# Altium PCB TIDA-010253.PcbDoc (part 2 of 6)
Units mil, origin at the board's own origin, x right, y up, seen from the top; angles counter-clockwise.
Board outline 5525 x 6695 mil, 4 copper layers (Top Layer, Signal Layer 1, Signal Layer 2, Bottom Layer), stack 61.2 mil thick; 522 components, 391 nets, 1722 pads, 1048 vias.
Unrouted connection lines stored in the file: 22.
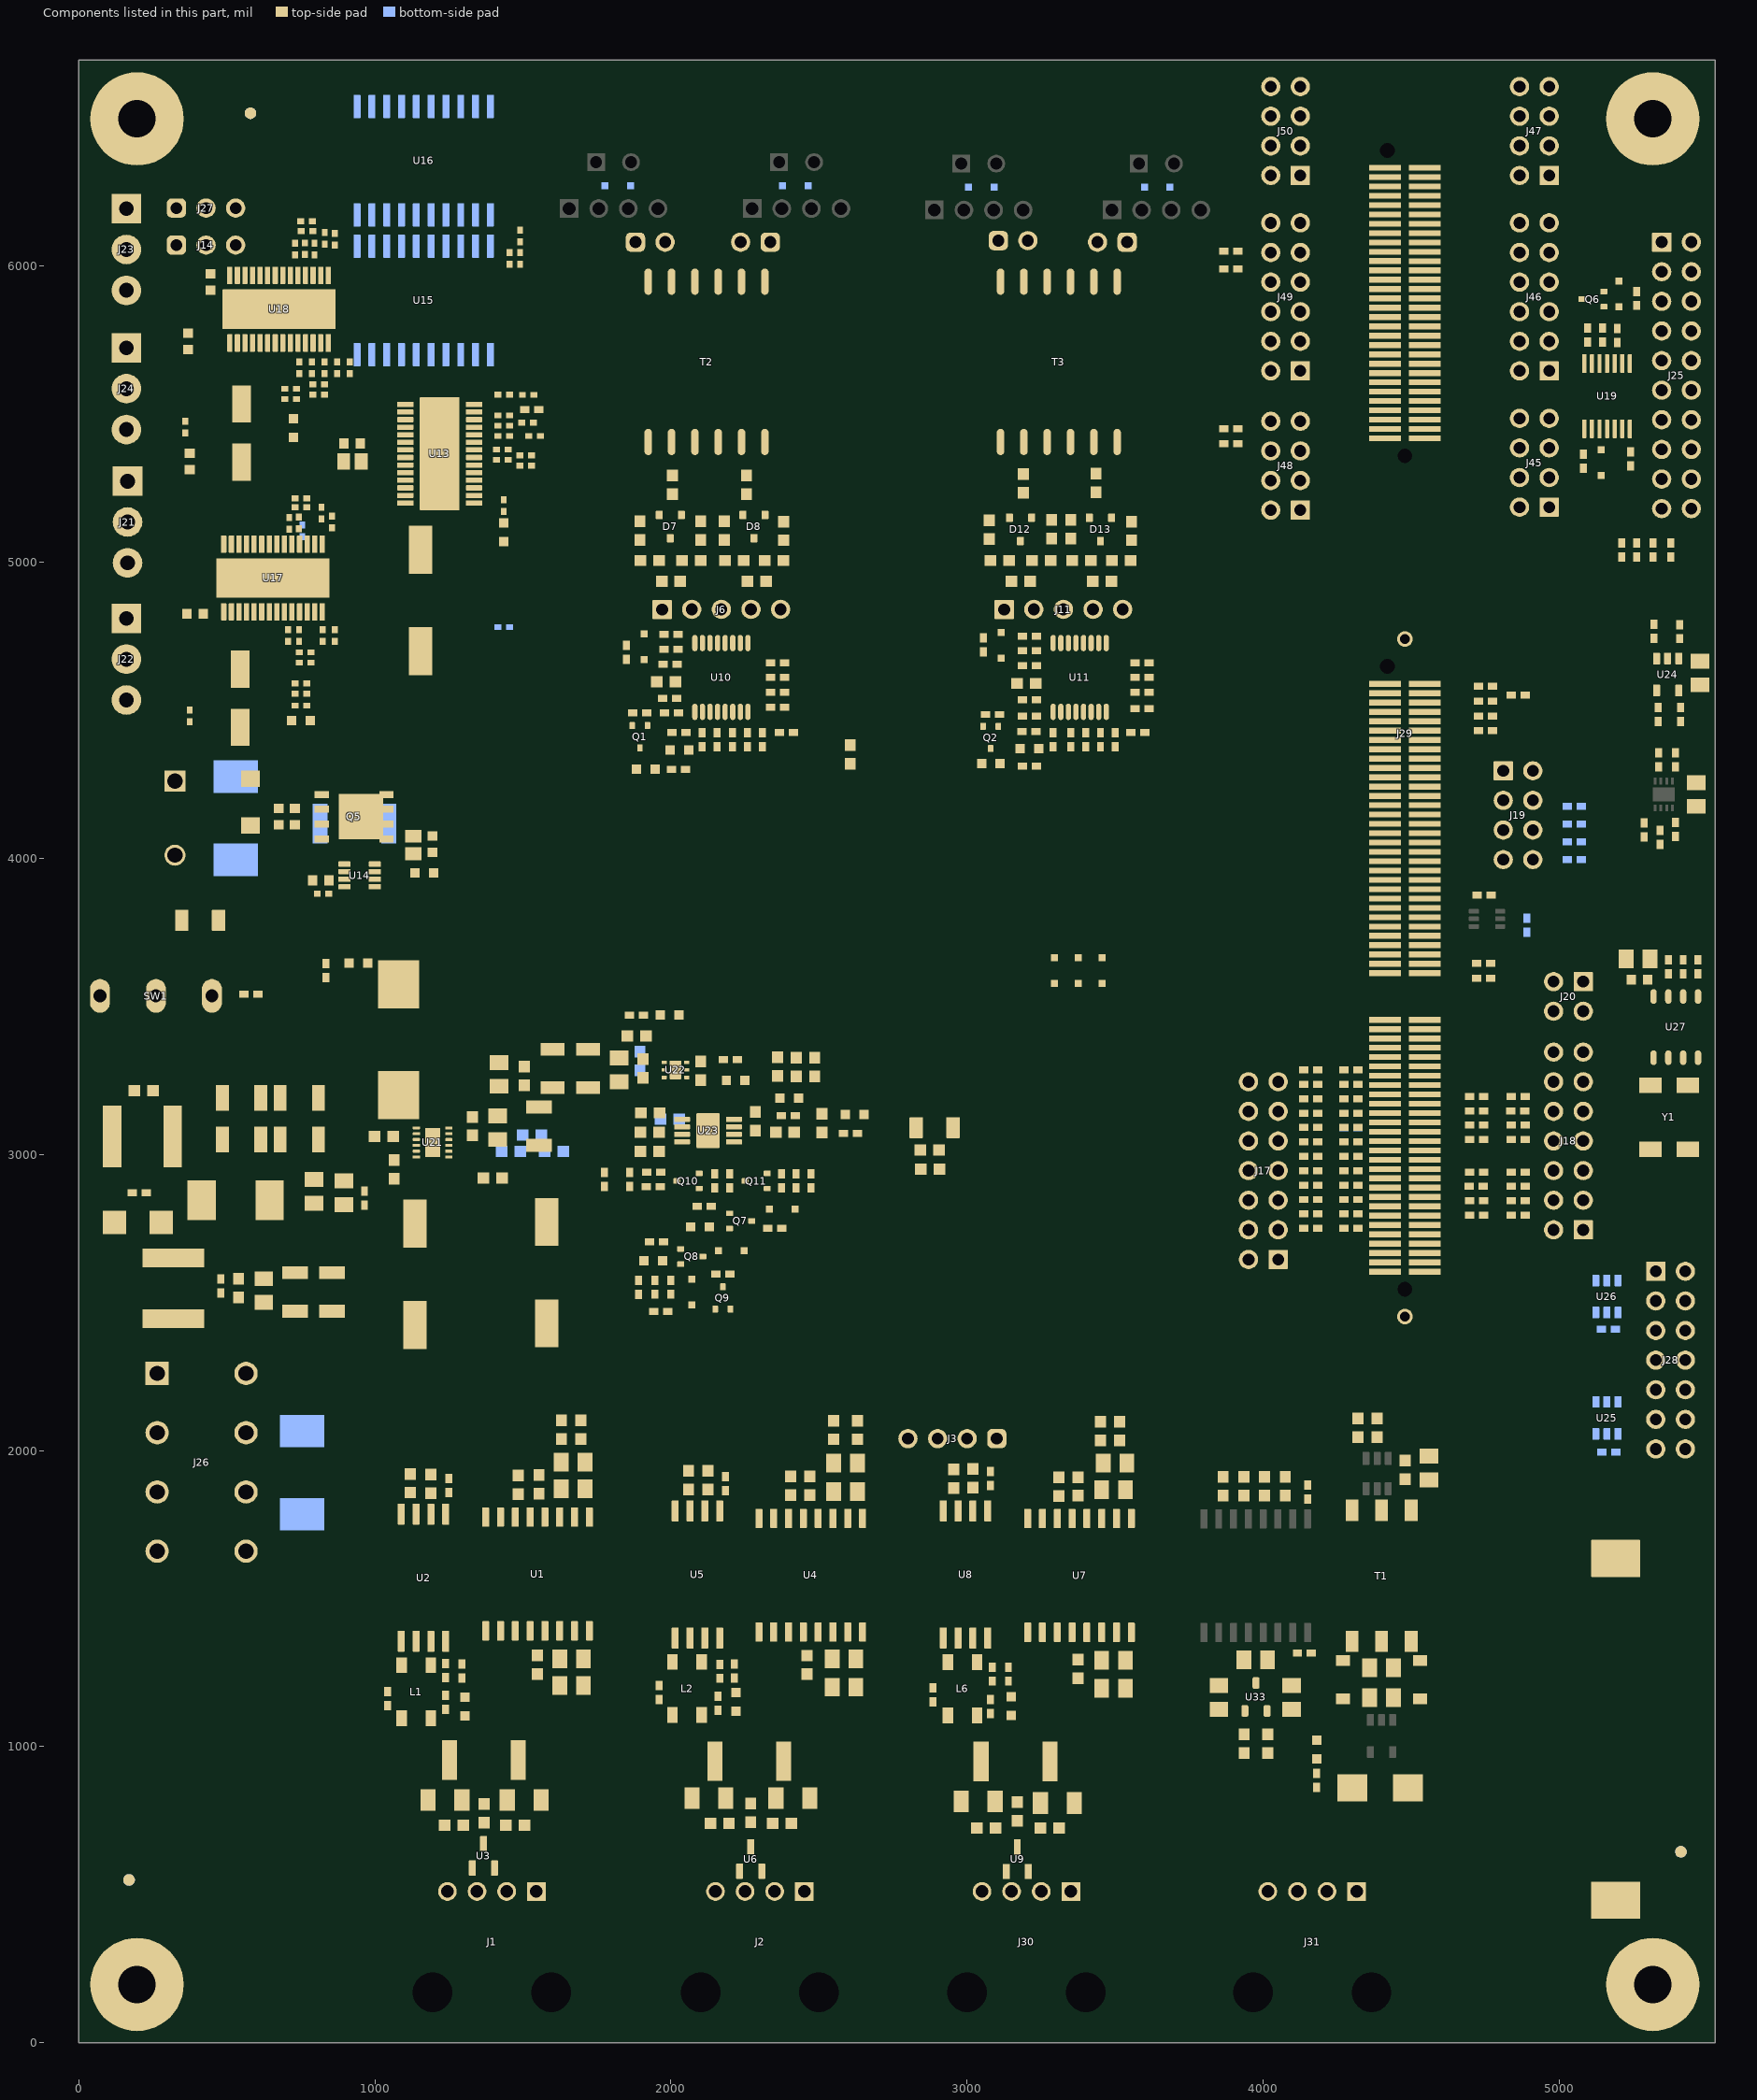
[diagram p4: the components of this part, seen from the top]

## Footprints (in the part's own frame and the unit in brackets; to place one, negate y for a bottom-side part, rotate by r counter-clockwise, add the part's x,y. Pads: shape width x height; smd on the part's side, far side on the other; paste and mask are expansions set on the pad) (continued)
FP-BU2032SM-G_SMT2-MFG [mm]
  rrect3% 3.2x4.2 smd paste+0 mask+0: 1(14.65,0) 2(-14.65,0)
  silkscreen extent -15.8,-8.25 14.55,8.25, body extent -15.8,-8 15.8,8, height 5.7
FP-DW0020A-MFG [mm]
  rrect17% 2x0.6 smd paste+0 mask+0: 1(-4.65,5.715) 2(-4.65,4.445) 3(-4.65,3.175) 4(-4.65,1.905) 5(-4.65,0.635) 6(-4.65,-0.635) 7(-4.65,-1.905) 8(-4.65,-3.175) 9(-4.65,-4.445) 10(-4.65,-5.715) 11(4.65,-5.715) 12(4.65,-4.445) 13(4.65,-3.175) 14(4.65,-1.905) 15(4.65,-0.635) 16(4.65,0.635) 17(4.65,1.905) 18(4.65,3.175) 19(4.65,4.445) 20(4.65,5.715)
  silkscreen extent -6.35,-6.5 3.27,6.5, body extent -5.16,-6.4 5.17,6.4, height 2.65
FP-GRM32ER71A476ME15L_1210-MFG [mm]
  rrect9% 1.1x2.05 smd paste+0 mask+0: 1(-1.65,0) 2(1.65,0)
  silkscreen extent -0.72,-1.35 0.72,1.35, body extent -2.3,-1.45 2.3,1.45, height 0.25
FP-PESD5V0L2BT,215_SOT23-3-MFG [mm]
  rrect17% 0.7x0.6 smd paste-1000 mask+0: 1(-1,0.95) 2(-1,-0.95) 3(1,0)
  body extent -1.5,-1.65 1.5,1.65, height 0.25
HEADER_HSEC8_180_DV [mm]
  rect 0.5x2.724 smd mask+0.076: 1(0,0) 2(0,3.4) 3(0.8,0) 4(0.8,3.4) 5(1.6,0) 6(1.6,3.4) 7(2.4,0) 8(2.4,3.4) 9(3.2,0) 10(3.2,3.4) 11(4,0) 12(4,3.4) 13(4.8,0) 14(4.8,3.4) 15(5.6,0) 16(5.6,3.4) 17(6.4,0) 18(6.4,3.4) 19(7.2,0) 20(7.2,3.4) 21(8,0) 22(8,3.4) 23(8.8,0) 24(8.8,3.4) 25(9.6,0) 26(9.6,3.4) 27(10.4,0) 28(10.4,3.4) 29(11.2,0) 30(11.2,3.4) 31(12,0) 32(12,3.4) 33(12.8,0) 34(12.8,3.4) 35(13.6,0) 36(13.6,3.4) 37(14.4,0) 38(14.4,3.4) 39(15.2,0) 40(15.2,3.4) 41(16,0) 42(16,3.4) 43(16.8,0) 44(16.8,3.4) 45(17.6,0) 46(17.6,3.4) 47(18.4,0) 48(18.4,3.4) 49(19.2,0) 50(19.2,3.4) 51(20,0) 52(20,3.4) 53(20.8,0) 54(20.8,3.4) 55(21.6,0) 56(21.6,3.4) 57(25.6,0) 58(25.6,3.4) 59(26.4,0) 60(26.4,3.4) 61(27.2,0) 62(27.2,3.4) 63(28,0) 64(28,3.4) 65(28.8,0) 66(28.8,3.4) 67(29.6,0) 68(29.6,3.4) 69(30.4,0) 70(30.4,3.4) 71(31.2,0) 72(31.2,3.4) 73(32,0) 74(32,3.4) 75(32.8,0) 76(32.8,3.4) 77(33.6,0) 78(33.6,3.4) 79(34.4,0) 80(34.4,3.4) 81(35.2,0) 82(35.2,3.4) 83(36,0) 84(36,3.4) 85(36.8,0) 86(36.8,3.4) 87(37.6,0) 88(37.6,3.4) 89(38.4,0) 90(38.4,3.4) 91(39.2,0) 92(39.2,3.4) 93(40,0) 94(40,3.4) 95(40.8,0) 96(40.8,3.4) 97(41.6,0) 98(41.6,3.4) 99(42.4,0) 100(42.4,3.4) 101(43.2,0) 102(43.2,3.4) 103(44,0) 104(44,3.4) 105(44.8,0) 106(44.8,3.4) 107(45.6,0) 108(45.6,3.4) 109(46.4,0) 110(46.4,3.4) 111(47.2,0) 112(47.2,3.4) 113(48,0) 114(48,3.4) 115(48.8,0) 116(48.8,3.4) 117(49.6,0) 118(49.6,3.4) 119(50.4,0) 120(50.4,3.4) 121(71.468,0) 122(71.468,3.4) 123(72.268,0) 124(72.268,3.4) 125(73.068,0) 126(73.068,3.4) 127(73.868,0) 128(73.868,3.4) 129(74.668,0) 130(74.668,3.4) 131(75.468,0) 132(75.468,3.4) 133(76.268,0) 134(76.268,3.4) 135(77.068,0) 136(77.068,3.4) 137(77.868,0) 138(77.868,3.4) 139(78.668,0) 140(78.668,3.4) 141(79.468,0) 142(79.468,3.4) 143(80.268,0) 144(80.268,3.4) 145(81.068,0) 146(81.068,3.4) 147(81.868,0) 148(81.868,3.4) 149(82.668,0) 150(82.668,3.4) 151(83.468,0) 152(83.468,3.4) 153(84.268,0) 154(84.268,3.4) 155(85.068,0) 156(85.068,3.4) 157(85.868,0) 158(85.868,3.4) 159(86.668,0) 160(86.668,3.4) 161(87.468,0) 162(87.468,3.4) 163(88.268,0) 164(88.268,3.4) 165(89.068,0) 166(89.068,3.4) 167(89.868,0) 168(89.868,3.4) 169(90.668,0) 170(90.668,3.4) 171(91.468,0) 172(91.468,3.4) 173(92.268,0) 174(92.268,3.4) 175(93.068,0) 176(93.068,3.4) 177(93.868,0) 178(93.868,3.4) 179(94.668,0) 180(94.668,3.4)
  round 0.025 hole 1.27 unplated mask+0.876: 181(-1.5,1.7) 182(51.9,3.2) 183(69.968,1.7) 184(96.168,3.2)
  round 1.348 hole 0.84: 185(-3.85,1.7) 186(54.25,1.7)
  silkscreen extent -8.76,-2.18 97.75,5.58
HMU2129NL [mm] "SOP, 12-Leads, Body 14.65x11.50mm, Pitch 2.00mm, IPC Low Density"
  oval 2.25x0.65 smd: 1(-6.875,5) 2(-6.875,3) 3(-6.875,1) 4(-6.875,-1) 5(-6.875,-3) 6(-6.875,-5) 7(6.875,-5) 8(6.875,-3) 9(6.875,-1) 10(6.875,1) 11(6.875,3) 12(6.875,5)
  silkscreen extent -7,-7.35 5.35,7.35
IEC_HighVoltage_Small [mil]
  silkscreen extent -107,-88 107,97
IHLP-2525CZ-5A [mil] "Vishay Dale recommended land pattern"
  rect 95x135 smd: 1(-114.96,0) 2(114.96,0)
  silkscreen extent -145,-136 145,136, body extent -143,-134 143,134, height 118
KF142R-5.08-4p [mm]
  round 2 hole 1.3: 1(0,7.62) 2(5.08,7.62) 2(5.08,0) 3(10.16,7.62) 3(10.16,0) 4(15.24,0) 4(15.24,7.62)
  rect 2x2 hole 1.3: 1(0,0)
  silkscreen extent -1.9,-4.2 22.04,9.45, body extent -0.76,-4.2 22.1,9.4, height 12.7
Label_650x200 [mil] "Thermal Transfer Label"
  round 1 on Mech13: 0(0,0)
  silkscreen extent -325,-100 325,100, body extent -325,-100 325,100, height 1
Molex_70551-0038 [mm] "Header(shrouded), 2.54mm, 4x1, R/A, TH"
  rect 1.6x1.6 hole 1.09: 1(0,3.81)
  round 1.6 hole 1.09: 2(0,1.27) 3(0,-1.27) 4(0,-3.81)
  round 0 hole 3.4 unplated paste+0 mask+0: MH1(8.64,-5.08) MH2(8.64,5.08)
  silkscreen extent 1.45,-6.98 12.88,7.32, body extent -0.71,-6.98 12.88,6.98, height 6.6
"NY PMS 440 0025 PH" [mm] "4-40 nylon screw and mounting hole"
  round 8 hole 3.2: 1(0,0)
  body extent -3.3,-3.3 3.3,3.3, height 2.69
Pb-Free_Overlay_Small [mil]
  silkscreen extent -46,-46 46,46
Phoenix_1714955 [mm] "Terminal Block, 2x1, 6.35mm, TH"
  rect 1.8x1.8 hole 1.3: 1(-3.175,0)
  round 1.8 hole 1.3: 2(3.175,0)
  silkscreen extent -6.7,-7.9 6.35,4.6, body extent -6.92,-7.9 6.35,4.6, height 21.5
PowerPAK_SO-8 [mil] "Vishay PowerPAK SO-8, Body 5.3x6.0mm (max), Pitch 1.27mm, IPC Medium Density"
  rect 50x24 smd mask+2.99: 1(-109.5,75) 2(-109.5,25) 3(-109.5,-25) 4(-109.5,-75)
  rect 48x24 smd mask+2.99: 5(109.5,-75) 8(109.5,75)
  rect 48x24 smd paste-12 mask+2.99: 6(109.5,-25) 7(109.5,25)
  rect 150x154 smd paste-75 mask+2.99: 9(22.5,0)
  silkscreen extent -130,-104 59,104, body extent -121,-102 121,101, height 43
PW0014A-MFG [mm]
  rrect29% 1.6x0.35 smd paste-1000 mask+0: 1(-2.8,1.95) 2(-2.8,1.3) 3(-2.8,0.65) 4(-2.8,0) 5(-2.8,-0.65) 6(-2.8,-1.3) 7(-2.8,-1.95) 8(2.8,-1.95) 9(2.8,-1.3) 10(2.8,-0.65) 11(2.8,0) 12(2.8,0.65) 13(2.8,1.3) 14(2.8,1.95)
  silkscreen extent -4.32,-2.55 2.25,2.55, body extent -3.7,-2.8 3.7,2.8, height 0.25
PW0016A_N [mm] "TSOP, 16-Leads, Body 5x4.4mm, Pitch 0.65mm, IPC Medium Density"
  oval 1.4x0.45 smd: 1(-2.95,2.275) 2(-2.95,1.625) 3(-2.95,0.975) 4(-2.95,0.325) 5(-2.95,-0.325) 6(-2.95,-0.975) 7(-2.95,-1.625) 8(-2.95,-2.275) 9(2.95,-2.275) 10(2.95,-1.625) 11(2.95,-0.975) 12(2.95,-0.325) 13(2.95,0.325) 14(2.95,0.975) 15(2.95,1.625) 16(2.95,2.275)
  silkscreen extent -3.5,-2.55 1.85,2.75, body extent -3.21,-2.5 3.21,2.5, height 1
PWP0028C_N [mm] "TSOP, 28-Leads, Body 9.7x4.4mm, Pitch 0.65mm, Exposed Pad, IPC Medium Density"
  rrect22% 1.4x0.45 smd: 1(-2.95,4.225) 2(-2.95,3.575) 3(-2.95,2.925) 4(-2.95,2.275) 5(-2.95,1.625) 6(-2.95,0.975) 7(-2.95,0.325) 8(-2.95,-0.325) 9(-2.95,-0.975) 10(-2.95,-1.625) 11(-2.95,-2.275) 12(-2.95,-2.925) 13(-2.95,-3.575) 14(-2.95,-4.225) 15(2.95,-4.225) 16(2.95,-3.575) 17(2.95,-2.925) 18(2.95,-2.275) 19(2.95,-1.625) 20(2.95,-0.975) 21(2.95,-0.325) 22(2.95,0.325) 23(2.95,0.975) 24(2.95,1.625) 25(2.95,2.275) 26(2.95,2.925) 27(2.95,3.575) 28(2.95,4.225)
  rrect3% 3.4x9.7 smd paste-1.7 mask-1.7: 29(0,0)
  rrect3% 3.1x5.18 on Top Solder: 29(0,0)
  rrect3% 3.1x5.18 on Top Paste: 29(0,0)
  silkscreen extent -3.5,-4.9 2,4.9, body extent -3.2,-4.85 3.2,4.85, height 1.13
PWP0028R-MFG [mm]
  rrect22% 1.5x0.45 smd paste+0 mask+0: 1(-2.9,4.225) 2(-2.9,3.575) 3(-2.9,2.925) 4(-2.9,2.275) 5(-2.9,1.625) 6(-2.9,0.975) 7(-2.9,0.325) 8(-2.9,-0.325) 9(-2.9,-0.975) 10(-2.9,-1.625) 11(-2.9,-2.275) 12(-2.9,-2.925) 13(-2.9,-3.575) 14(-2.9,-4.225) 15(2.9,-4.225) 16(2.9,-3.575) 17(2.9,-2.925) 18(2.9,-2.275) 19(2.9,-1.625) 20(2.9,-0.975) 21(2.9,-0.325) 22(2.9,0.325) 23(2.9,0.975) 24(2.9,1.625) 25(2.9,2.275) 26(2.9,2.925) 27(2.9,3.575) 28(2.9,4.225)
  rrect3% 3.4x9.7 smd paste-1000 mask-1000: 29(0,0)
  silkscreen extent -4.37,-4.9 2.25,4.9, body extent -3.75,-5.15 3.75,5.15, height 0.25
SM_RADIAL_D [mm] "6.3 x 5.8mm:  Panasonic D"
  rect 3.2x1.6 smd: 1(-2.5,0) 2(2.5,0)
  silkscreen extent -3.4,-3.4 3.4,3.4, body extent -3.4,-3.4 3.4,3.4, height 6.1
SM_RADIAL_G [mm] "10 x 10.2mm:  Panasonic G"
  rect 4.1x2 smd: 1(-4.35,0) 2(4.35,0)
  silkscreen extent -5.35,-5.35 5.35,5.35, body extent -5.25,-5.25 5.25,5.25, height 10.5
SMA [mm] "Molded Diode, 2-Leads, Body 4.3x2.6mm, IPC Medium Density, based on OnSemi component dimensions and land pattern"
  rect 2x2 smd: 1(-2,0) 2(2,0)
  silkscreen extent -3.66,-1.57 2.79,1.57, body extent -2.6,-1.3 2.6,1.3, height 2.42
SMA_Bi [mm] "SMD, 2-Leads, Body 4.275x2.575mm"
  rect 1.4x1.64 smd: 1(-2.015,0) 2(2.015,0)
  silkscreen extent -2.3,-1.45 2.3,1.45, body extent -2.52,-1.45 2.52,1.45, height 2.65
SMC_Bi [mil] "SMC, no polarity mark"
  rect 110x150 smd: 1(-140.49,0) 2(140.49,0)
  body extent -156,-116 156,116, height 92
SOD-123 [mm] "On Semi recommended land pattern"
  rect 0.915x1.22 smd: 1(-1.637,0) 2(1.637,0)
  silkscreen extent -2.74,-1.17 2.03,1.17, body extent -1.93,-0.9 1.93,0.9, height 1.35
SOD-323 [mm] "NXP recommended land pattern"
  rect 0.6x0.6 smd paste-0.05: 1(-1.1,0) 2(1.1,0)
  silkscreen extent -2.06,-0.86 1.53,0.86, body extent -1.3,-0.67 1.3,0.68, height 1.1
SOD-323-Bi [mm] "SOD323, 2-Leads, Body 1.9x1.45mm, No Polarity Mark"
  rect 0.6x0.6 smd paste-0.05: 1(-1.1,0) 2(1.1,0)
  silkscreen extent -1.53,-0.77 1.53,0.77, body extent -1.27,-0.65 1.27,0.65, height 1.02
SOT-23 [mm] "SOT23, 3-Leads, Body 2.9x1.3mm, Pitch 0.95mm, Lead Span 2.5mm, IPC Medium Density"
  rrect50% 1x0.6 smd: 1(-1.2,0.95) 2(-1.2,-0.95) 3(1.2,0)
  silkscreen extent -1.62,-1.5 0.7,1.5, body extent -1.16,-1.45 1.21,1.45, height 1
SOT-323 [mm] "Diodes Inc recommended land pattern.  2016-02-24"
  rrect21% 0.6x0.47 smd: 1(-0.95,0.65) 2(-0.95,-0.65) 3(0.95,0)
  silkscreen extent -1.14,-1.22 0.77,1.22, body extent -1.13,-1.13 1.12,1.12, height 1.13
SS12D10 [mm]
  oval 1.7x2.9 hole 1.1 slot 2.3 at 90 deg paste+0 mask+0.05: 1(-4.8,0) 2(0,0) 3(4.8,0)
  silkscreen extent -6.5,-3.5 6.5,3.5, body extent -6.5,-3.4 6.5,3.4, height 16.4
TERM_BLK_ED555-3DS [mm]
  rect 2.54x2.54 hole 1.27: 1(0,0)
  round 2.54 hole 1.27: 2(3.5,0) 3(7,0)
  silkscreen extent -2.36,-4.09 8.75,2.67, body extent -1.75,-3.83 8.75,2.67, height 8.2
TSW-102-07-G-D [mm] "Samtec 100mil, 2x2, 230 mil above insulator"
  rrect6% 1.65x1.65 hole 1.016: 1(-1.27,-1.27)
  round 1.65 hole 1.016: 2(-1.27,1.27) 3(1.27,-1.27) 4(1.27,1.27)
  silkscreen extent -3.57,-2.54 2.54,2.54, body extent -2.54,-2.54 2.54,2.54, height 8.38
TSW-102-07-G-S [mm] "Samtec 100mil, 1x2, 230 mil above insulator"
  rrect50% 1.65x1.65 hole 1.016: 1(-1.27,0)
  round 1.65 hole 1.016: 2(1.27,0)
  silkscreen extent -3.17,-1.27 2.54,1.27, body extent -2.54,-1.27 2.54,1.27, height 8.38
TSW-103-07-G-S [mm] "Samtec 100mil, 1x3, 230 mil above insulator"
  rrect50% 1.65x1.65 hole 1.016: 1(-2.54,0)
  round 1.65 hole 1.016: 2(0,0) 3(2.54,0)
  body extent -3.81,-1.27 3.81,1.27, height 8.38
TSW-104-07-G-D [mm] "Samtec 100mil, 2x4, 230 mil above insulator"
  rrect6% 1.65x1.65 hole 1.016: 1(-3.81,-1.27)
  round 1.65 hole 1.016: 2(-3.81,1.27) 3(-1.27,-1.27) 4(-1.27,1.27) 5(1.27,-1.27) 6(1.27,1.27) 7(3.81,-1.27) 8(3.81,1.27)
  silkscreen extent -6.1,-2.54 5.08,2.54, body extent -5.08,-2.54 5.08,2.54, height 8.38
TSW-104-07-G-S [mm] "Samtec 100mil, 1x4, 230 mil above insulator"
  rrect50% 1.65x1.65 hole 1.016: 1(-3.81,0)
  round 1.65 hole 1.016: 2(-1.27,0) 3(1.27,0) 4(3.81,0)
  body extent -5.08,-1.27 5.08,1.27, height 8.38
TSW-105-07-X-S [mm] "Samtec 100mil, 1x5, 230 mil above insulator"
  rrect6% 1.65x1.65 hole 1.016: 1(-5.08,-0.025)
  round 1.65 hole 1.016: 2(-2.54,0) 3(0,0) 4(2.54,0) 5(5.08,0)
  silkscreen extent -7.05,-1.25 6.37,1.25, body extent -6.35,-1.27 6.35,1.27, height 8.38
TSW-106-07-G-D [mm] "Samtec 100mil, 2x6, 230 mil above insulator"
  rrect6% 1.65x1.65 hole 1.016: 1(-6.35,-1.27)
  round 1.65 hole 1.016: 2(-6.35,1.27) 3(-3.81,-1.27) 4(-3.81,1.27) 5(-1.27,-1.27) 6(-1.27,1.27) 7(1.27,-1.27) 8(1.27,1.27) 9(3.81,-1.27) 10(3.81,1.27) 11(6.35,-1.27) 12(6.35,1.27)
  silkscreen extent -8.64,-2.54 7.62,2.54, body extent -7.62,-2.54 7.62,2.54, height 8.38
TSW-107-07-X-D [mm] "Samtec 100mil, 2x7, 230 mil above insulator"
  rrect6% 1.65x1.65 hole 1.016: 1(-7.62,-1.27)
  round 1.65 hole 1.016: 2(-7.62,1.27) 3(-5.08,-1.27) 4(-5.08,1.27) 5(-2.54,-1.27) 6(-2.54,1.27) 7(0,-1.27) 8(0,1.27) 9(2.54,-1.27) 10(2.54,1.27) 11(5.08,-1.27) 12(5.08,1.27) 13(7.62,-1.27) 14(7.62,1.27)
  silkscreen extent -9.91,-2.53 9.14,2.5, body extent -8.89,-2.54 8.89,2.54, height 8.38
TSW-110-07-G-D [mm] "Samtec 100mil, 2x10, 230 mil above insulator"
  rrect6% 1.65x1.65 hole 1.016: 1(-11.43,-1.27)
  round 1.65 hole 1.016: 2(-11.43,1.27) 3(-8.89,-1.27) 4(-8.89,1.27) 5(-6.35,-1.27) 6(-6.35,1.27) 7(-3.81,-1.27) 8(-3.81,1.27) 9(-1.27,-1.27) 10(-1.27,1.27) 11(1.27,-1.27) 12(1.27,1.27) 13(3.81,-1.27) 14(3.81,1.27) 15(6.35,-1.27) 16(6.35,1.27) 17(8.89,-1.27) 18(8.89,1.27) 19(11.43,-1.27) 20(11.43,1.27)
  silkscreen extent -13.72,-2.54 12.7,2.54, body extent -12.7,-2.54 12.7,2.54, height 8.38
WE-LHMI_1040 [mm] "Wurth"
  rect 4.1x3.5 smd: 1(-4.75,0) 2(4.75,0)
  silkscreen extent -5.5,-5.15 5.5,5.15, body extent -5.5,-5.15 5.5,5.15, height 4
WEEE_Minimum [mil] "WEEElie bin"
  silkscreen extent -95,-172 99,104
WL-SMCW_GREEN [mm] "WURTH"
  rect 0.8x0.8 smd: 1(-0.8,0) 2(0.8,0)
  silkscreen extent -1.9,-0.8 1.2,0.8, body extent -0.85,-0.45 0.85,0.45, height 0.8
WL-SMCW_RED [mm] "WURTH"
  rect 0.8x0.8 smd: 1(-0.8,0) 2(0.8,0)
  silkscreen extent -1.9,-0.8 1.2,0.8, body extent -0.85,-0.45 0.85,0.45, height 0.8
Wurth_750315371 [mm] "SMD, Body 12.6x8.3mm, Pitch 2.54mm"
  rect 1.83x1.09 smd: 1(-5.62,2.54) 2(-5.62,0) 3(-5.62,-2.54) 4(5.62,-2.54) 5(5.62,0) 6(5.62,2.54)
  silkscreen extent -6.3,-4.15 6.3,4.4, body extent -6.35,-4.2 6.35,4.2, height 4.11
XTAL_MC-306 [mm] "SEIKO-EPSON"
  rect 1.9x1.3 smd: 1(-1.6,2.75) 2(-1.6,-2.75) 3(1.6,-2.75) 4(1.6,2.75)
  silkscreen extent -1.6,-4 1.6,4, body extent -1.6,-4 1.6,4, height 2.55

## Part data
BT1: library part CMP-0032780-1, "Battery Holder Coin 20MM SMD", Digikey Part Number=BU2032SM-GCT-ND, Manufacturer=MPD, Operating Temperature Range="-40°C to +280°C"
C1 C2 C8 C9 C15 C16 C109 C110 C111 C112 C117 C118 C119 C120 C121 C122 C123 C124 C125 C128 C129 C131 C132 C133 C134 C138 C139 C144 C145 C146 C147: library part CMP-0006350-2, "CAP, CERM, 0.1 uF, 10 V, +/- 10%, X7R, AEC-Q200 Grade 1, 0402", Cap_Case=0402, Manufacturer=MuRata, Supplier Part Number 1=81-GCM155R71A104K5D, TempCo=X7R, Tolerance_%=10%, Value1=Unknown, Value2=10V, ValueDisplayed=0.1uF
C3 C4 C10 C11 C17 C18 C140 C141: library part CMP-0007995-2, "CAP, CERM, 10 uF, 16 V, +/- 10%, X7R, 0805", Cap_Case=0805, Manufacturer="Samsung Electro-Mechanics", TempCo=X7R, Tolerance_%=10%, Value1=Unknown, Value2=16V, ValueDisplayed=10uF
C5 C7 C12 C14 C135 C137: library part CMP-0007280-4, "CAP, CERM, 68 pF, 100 V, +/- 5%, C0G/NP0, 0603", Cap_Case=0603, Manufacturer=MuRata, Supplier Part Number 1=490-1347-1-ND, TempCo=C0G/NP0, Tolerance_%=5%, Value1=Unknown, Value2=100V, ValueDisplayed=68pF
C6 C13 C136: library part CMP-0007456-1, "CAP, CERM, 4700 pF, 50 V, +/- 10%, X7R, 0603", Cap_Case=0603, Manufacturer=MuRata, Supplier Part Number 1=490-1506-1-ND, TempCo=X7R, Tolerance_%=10%, Value1=Unknown, Value2=50V, ValueDisplayed=4700pF
C19 C25 C30 C36 C75 C101 C105 C106: library part CMP-0006356-2, "CAP, CERM, 0.1 uF, 50 V, +/- 10%, X7R, AEC-Q200 Grade 1, 0402", Cap_Case=0402, Manufacturer=MuRata, Supplier Part Number 1=490-10672-1-ND, TempCo=X7R, Tolerance_%=10%, Value1=Unknown, Value2=50V, ValueDisplayed=0.1uF
C20 C24 C26 C28 C31 C35 C37 C39: library part CMP-0860329-1, "CAP, CERM, 220 pF, 50 V,+/- 5%, X7R, 0603", Cap_Case=0603, Manufacturer="Samsung Electro-Mechanics", TempCo=X7R, Tolerance_%=5%, Value2=50V, ValueDisplayed=220pF
C21 C27 C32 C38: library part CMP-0750041-1, "CAP, CERM, 100 pF, 50 V,+/- 5%, C0G/NP0, AEC-Q200 Grade 1, 0603", Cap_Case=0603, Manufacturer=MuRata, TempCo=C0G/NP0, Tolerance_%=5%, Value2=50V, ValueDisplayed=100pF
C22 C23 C33 C34: library part CMP-0078265-1, "CAP, CERM, 0.22 µF, 16 V,+/- 10%, X7R, AEC-Q200 Grade 1, 0402", Cap_Case=0402, Manufacturer=MuRata, Supplier Part Number 1=490-10671-1-ND, TempCo=X7R, Tolerance_%=10%, Value2=16V, ValueDisplayed=0.22µF
C29 C40: library part CMP-0006324-2, "CAP, CERM, 0.01 uF, 50 V, +/- 10%, X7R, AEC-Q200 Grade 1, 0402", Cap_Case=0402, Manufacturer=TDK, Supplier Part Number 1=445-6893-1-ND, TempCo=X7R, Tolerance_%=10%, Value1="0.333065 ohm", Value2=50V, ValueDisplayed=0.01uF
C47 C51: library part CMP-0006837-4, "CAP, CERM, 0.1 uF, 50 V, +/- 10%, X7R, 0603", Cap_Case=0603, Manufacturer="Wurth Elektronik", TempCo=X7R, Tolerance_%=10%, Value1=Unknown, Value2=50V, ValueDisplayed=0.1uF
C48 C53: library part CMP-0007857-1, "CAP, CERM, 2.2 uF, 50 V, +/- 10%, X6S, 0805", Cap_Case=0805, Manufacturer=TDK, Supplier Part Number 1=445-7597-1-ND, TempCo=X6S, Tolerance_%=10%, Value1="0.00366 ohm", Value2=50V, ValueDisplayed=2.2uF
C49: library part CMP-0006783-4, "CAP, CERM, 33 pF, 50 V, +/- 5%, C0G/NP0, 0603", Cap_Case=0603, Manufacturer=AVX, Supplier Part Number 1=478-1169-1-ND, TempCo=C0G/NP0, Tolerance_%=5%, Value1="0.209 ohm", Value2=50V, ValueDisplayed=33pF
C50: library part CMP-0006840-4, "CAP, CERM, 100 pF, 50 V, +/- 5%, C0G/NP0, 0603", Cap_Case=0603, Manufacturer=Kemet, Supplier Part Number 1=1414602, TempCo=C0G/NP0, Tolerance_%=5%, Value1=Unknown, Value2=50V, ValueDisplayed=100pF
C52 C108: library part CMP-0082523-1, "CAP, CERM, 1 µF, 25 V,+/- 10%, X7R, AEC-Q200 Grade 1, 0603", Cap_Case=0603, Manufacturer=TDK, Supplier Part Number 1=445-9819-1-ND, TempCo=X7R, Tolerance_%=10%, Value2=25V, ValueDisplayed=1µF
C54: library part CMP-0022330-4, "RES, 31.6 k, 1%, 0.1 W, AEC-Q200 Grade 0, 0603", Manufacturer=Vishay-Dale, Power_W=100mW, Supplier Part Number 1=541-31.6KHCT-ND, TempCo="100 ppm/C", Tolerance_%=1%, Value2=0.1W, Value_Code=31k6, ValueDisplayed=31.6k
C59: library part CMP-0011178-2, "CAP, AL, 150 uF, 50 V, +/- 20%, 0.18 ohm, AEC-Q200 Grade 2, SMD", Cap_Case=G, Manufacturer=Panasonic, Supplier Part Number 1=PCE3810CT-ND, Tolerance_%=20%, Value1="0.18 ohm", Value2=50V, ValueDisplayed=150uF
C60 C61: library part CMP-0011175-2, "CAP, AL, 10 uF, 50 V, +/- 20%, 0.88 ohm, AEC-Q200 Grade 2, SMD", Cap_Case=D, Manufacturer=Panasonic, Supplier Part Number 1=PCE3807CT-ND, Tolerance_%=20%, Value1="0.88 ohm", Value2=50V, ValueDisplayed=10uF
C62 C63 C64 C65: library part CMP-0064946-2, "CAP, CERM, 0.1 uF, 50 V,+/- 10%, X7R, 0402", Cap_Case=0402, Manufacturer=TDK, Supplier Part Number 1=445-173610-1-ND, TempCo=X7R, Tolerance_%=10%, Value1=Unknown, Value2=50V, ValueDisplayed=0.1uF
C66 C67 C68 C69 C70: library part CMP-0006691-2, "CAP, CERM, 470 pF, 50 V, +/- 10%, X7R, 0402", Cap_Case=0402, Manufacturer=MuRata, Supplier Part Number 1=490-1300-1-ND, TempCo=X7R, Tolerance_%=10%, Value1=Unknown, Value2=50V, ValueDisplayed=470pF
C71 C72 C73 C74: library part CMP-0006844-4, "CAP, CERM, 1000 pF, 50 V, +/- 5%, X7R, AEC-Q200 Grade 1, 0603", Cap_Case=0603, Manufacturer=Kemet, Supplier Part Number 1=399-12989-1-ND, TempCo=X7R, Tolerance_%=5%, Value1=Unknown, Value2=50V, ValueDisplayed=1000pF
C76 C77: library part CMP-0010742-1, "CAP, AL, 220 uF, 35 V, +/- 20%, 0.15 ohm, AEC-Q200 Grade 1, SMD", Cap_Case=10x10.2mm, Manufacturer=Panasonic, Supplier Part Number 1=PCE4935CT-ND, Tolerance_%=20%, Value1="0.15 ohm", Value2=35V, ValueDisplayed=220uF
C78: library part CMP-0007088-4, "CAP, CERM, 4700 pF, 100 V, +/- 10%, X7R, AEC-Q200 Grade 1, 0603", Cap_Case=0603, Manufacturer=TDK, Supplier Part Number 1=445-5810-1-ND, TempCo=X7R, Tolerance_%=10%, Value1="0.469862 ohm", Value2=100V, ValueDisplayed=4700pF
C79 C81: library part CMP-0009420-2, "CAP, CERM, 15 uF, 100 V, +/- 20%, X7S, AEC-Q200 Grade 1, 2220", Cap_Case=2220_280, Manufacturer=TDK, Supplier Part Number 1=445-7948-1-ND, TempCo=X7S, Tolerance_%=20%, Value1="0.002642 ohm", Value2=100V, ValueDisplayed=15uF
C80: library part CMP-0006412-2, "CAP, CERM, 1000 pF, 50 V, +/- 5%, C0G/NP0, 0402", Cap_Case=0402, Manufacturer=MuRata, Supplier Part Number 1=490-3244-1-ND, TempCo=C0G/NP0, Tolerance_%=5%, Value1=Unknown, Value2=50V, ValueDisplayed=1000pF
C82 C83 C87 C88 C89 C90: library part CMP-0009164-2, "CAP, CERM, 10 uF, 50 V, +/- 10%, X7S, AEC-Q200 Grade 1, 1210", Cap_Case=1210_280, Manufacturer=TDK, Supplier Part Number 1=445-7004-1-ND, TempCo=X7S, Tolerance_%=10%, Value1="0.002827 ohm", Value2=50V, ValueDisplayed=10uF
C84 C91 C92: library part CMP-0007977-2, "CAP, CERM, 2.2 uF, 50 V, +/- 10%, X7R, AEC-Q200 Grade 1, 0805", Cap_Case=0805, Manufacturer=TDK, Supplier Part Number 1=445-174216-1-ND, TempCo=X7R, Tolerance_%=10%, Value1="0.003288 ohm", Value2=50V, ValueDisplayed=2.2uF
C85: library part CMP-0084240-1, "CAP, CERM, 0.1 µF, 50 V,+/- 20%, X8R, AEC-Q200 Grade 0, 0603", Cap_Case=0603, Manufacturer=TDK, TempCo=X8R, Tolerance_%=20%, Value2=50V, ValueDisplayed=0.1µF
C86 C93: library part CMP-0006309-2, "CAP, CERM, 1000 pF, 50 V, +/- 5%, C0G/NP0, AEC-Q200 Grade 1, 0402", Cap_Case=0402, Manufacturer=TDK, Supplier Part Number 1=445-6885-1-ND, TempCo=C0G/NP0, Tolerance_%=5%, Value1=Unknown, Value2=50V, ValueDisplayed=1000pF
C96: library part CMP-0009162-2, "CAP, CERM, 4.7 uF, 50 V, +/- 10%, X7R, AEC-Q200 Grade 1, 1210", Cap_Case=1210_280, Manufacturer=TDK, Supplier Part Number 1=445-6999-1-ND, TempCo=X7R, Tolerance_%=10%, Value1="0.003166 ohm", Value2=50V, ValueDisplayed=4.7uF
C97 C107 C142 C143 CO1 CO2 CO3 CO4 CO5 CO8 CO10 CO11 CO12: library part CMP-0007631-2, "CAP, CERM, 0.1 uF, 50 V, +/- 5%, X7R, 0805", Cap_Case=0805, Manufacturer=AVX, Supplier Part Number 1=478-3352-1-ND, TempCo=X7R, Tolerance_%=5%, Value1="0.024 ohm", Value2=50V, ValueDisplayed=0.1uF
C98 C104 CO9: library part CMP-0064933-4, "CAP, CERM, 1000 pF, 50 V,+/- 10%, X7R, 0603", Cap_Case=0603, Manufacturer="Wurth Elektronik", Supplier Part Number 1=732-8001-1-ND, TempCo=X7R, Tolerance_%=10%, Value1=Unknown, Value2=50V, ValueDisplayed=1000pF
C99 C102: library part CMP-0007136-5, "CAP, CERM, 1 uF, 16 V, +/- 10%, X7R, AEC-Q200 Grade 1, 0603", Cap_Case=0603, Manufacturer=MuRata, Supplier Part Number 1=490-5241-6-ND, TempCo=X7R, Tolerance_%=10%, Value1=Unknown, Value2=16V, ValueDisplayed=1uF
C100 C103: library part CMP-0081052-1, "CAP, CERM, 4.7 µF, 16 V,+/- 10%, X5R, AEC-Q200 Grade 3, 0603", Cap_Case=0603, Manufacturer=MuRata, Supplier Part Number 1=490-12319-1-ND, TempCo=X5R, Tolerance_%=10%, Value2=16V, ValueDisplayed=4.7µF
C113: library part CMP-0006752-5, "CAP, CERM, 0.1 uF, 25 V, +/- 5%, X7R, 0603", Cap_Case=0603, Manufacturer=AVX, Supplier Part Number 1=478-3713-1-ND, TempCo=X7R, Tolerance_%=5%, Value1="0.05 ohm", Value2=25V, ValueDisplayed=0.1uF
C114: library part CMP-0011667-2, "CAP, TA, 4.7 uF, 35 V, +/- 10%, 0.6 ohm, SMD", Cap_Case=C, Manufacturer=AVX, Supplier Part Number 1=478-1772-1-ND, Tolerance_%=10%, Value1="0.6 ohm", Value2=35V, ValueDisplayed=4.7uF
CBoot1: library part CMP-0006802-4, "CAP, CERM, 0.1 uF, 50 V, +/- 10%, X7R, 0603", Cap_Case=0603, Manufacturer=AVX, Supplier Part Number 1=478-5052-1-ND, TempCo=X7R, Tolerance_%=10%, Value1=Unknown, Value2=50V, ValueDisplayed=0.1uF
CO6 CO7: library part CMP-0088887-1, "47µF ±20% 10V Ceramic Capacitor X7R 1210 (3225 Metric)", Digikey Part Number=490-6543-1-ND, Manufacturer=Murata, Mouser Part Number=81-GRM32ER71A476ME5L, Operating Temperature Range="-55°C to +125°C", TempCo=15%, Temperature Characteristic=X7R, Tolerance_%=20%, ValueDisplayed=47uF
D1 D2 D3 D5 D11 D16 D34 D35 D37 D38 D39: library part CMP-0002947-3, "LED, Red, SMD", Color=Red, Manufacturer="Wurth Elektronik", Power_TotalModule=72mW, Value1=0.072W, Value2=2V
D4 D6: library part CMP-0028360-2, "Diode, Schottky, 40 V, 1 A, SOD-123", Manufacturer="Diodes Inc.", Value1=1A, Value2=0.45V
D7 D8 D12 D13: library part CMP-0086523-1, "28V Clamp 13A (8/20µs) Ipp Tvs Diode Surface Mount TO-236AB", Manufacturer=Nexperia
D9 D14 D23 D28 D29 D30: library part CMP-0085730-1, "Diode, Zener, 3.3 V, 300 mW, AEC-Q101, SOD-323", Manufacturer="ON Semiconductor", Power_W=300mW, Value1=0.3W
D10 D15 D19 D26 D27: library part CMP-0002894-2, "LED, Green, SMD", Color=green, Manufacturer="Wurth Elektronik", Value1=W, Value2=2V
D17: library part CMP-0085017-1, "Diode, TVS, Bi, 36 V, 58.1 Vc, 400 W, 6.9 A, SMA (non-polarized)", Manufacturer=Littelfuse, Value1=58.1V
D18: library part CMP-0005695-3, "Diode, TVS, Bi, 33 V, SMC", Manufacturer=Bourns, Value1=1500W
D20 D21 D22: library part CMP-0002893-1, "LED, Super Red, SMD", Color="super red", Manufacturer="Wurth Elektronik", Supplier Part Number 1=732-4979-1-ND, Value1=W, Value2=1.9V
D24: library part CMP-0081199-2, "Diode, Schottky, 30 V, 0.1 A, AEC-Q101, SOD-323", Manufacturer="Diodes Inc.", Value1=0.1A, Value2=1V
D25: library part CMP-0028854-2, "Diode, Schottky, 60 V, 3 A, AEC-Q101, SMA", Manufacturer=Rohm, Value1=3A, Value2=0.64V
D31 D32 D33: library part CMP-0079597-2, "Diode, Switching, 75 V, 0.15 A, AEC-Q101, SOD-323", Manufacturer="Diodes Inc.", Value1=0.15A, Value2=1.25V
D36: library part CMP-0005697-3, "Diode, TVS, Bi, 36 V, 58.1 Vc, SMC", Manufacturer=Littelfuse, Value1=1500W
D40 D41 D42 D43: library part CMP-0065114-2, "Diode, TVS, Bi, 8 V, 18.5 Vc, SOD-323", Manufacturer=Bourns, PartNumber=TSD05CDYFR, Value1=400W
F1 F2: library part CMP-0091575-1, "Chip Ferrite Bead, 1206, 120Ω @ 100MHz, 0.009Ω, 25%, 6A", Impedance At Frequency="120Ω @ 100MHz", Manufacturer=Murata, Operating Temperature Range="-55°C to +125℃", Test Frequency=100MHz, Tolerance_%=25%
FID1 FID2 FID3 FID4 FID5 FID6: library part CMP-0077181-1, "Fiducial mark.  There is nothing to buy or mount.", Manufacturer=N/A
H1 H2 H3 H4: library part CMP-0003617-1, "Machine Screw, Round, #4-40 x 1/4, Nylon, Philips panhead", Manufacturer="B&F Fastener Supply", Supplier Part Number 1=H542-ND
J1 J2 J30 J31: library part CMP-0055239-1, "Header(shrouded), 2.54mm, 4x1, R/A, Gold, TH", Color=Black, Current_A=3A, Manufacturer=Molex, Supplier Part Number 1=0705510038-ND, Voltage_V=250V
J3: library part CMP-0075409-2, "Header, 100mil, 4x1, Gold, TH", Color=Black, Current_A=6.3A, Manufacturer=Samtec, Supplier Part Number 1=SAM1029-04-ND, Voltage_V=550V
J5 J7 J10 J12: library part CMP-0075405-3, "Header, 100mil, 2x1, Gold, TH", Color=Black, Current_A=6.3A, Manufacturer=Samtec, Supplier Part Number 1=SAM1029-02-ND, Voltage_V=550V
J6 J11: library part CMP-0075411-1, "Header, 100mil, 5x1, Gold, TH", Color=Black, Current_A=6.3A, Manufacturer=Samtec, Supplier Part Number 1=SAM1029-05-ND, Voltage_V=550V
J14 J27: library part CMP-0075407-2, "Header, 100mil, 3x1, Gold, TH", Color=Black, Current_A=6.3A, Manufacturer=Samtec, Supplier Part Number 1=SAM1029-03-ND, Voltage_V=550V
J16: library part CMP-0055505-1, "Terminal Block, 2x1, 6.35mm, Green, TH", Color=Green, Manufacturer="Phoenix Contact", Supplier Part Number 1=277-1269-ND
J17 J18 J28: library part CMP-0075415-2, "Header, 100mil, 7x2, Gold, TH", Color=Black, Current_A=6.3A, Manufacturer=Samtec, Supplier Part Number 1=SAM1028-07-ND, Voltage_V=550V
J19 J45 J47 J48 J50: library part CMP-0075408-3, "Header, 100mil, 4x2, Gold, TH", Color=Black, Current_A=6.3A, Manufacturer=Samtec, Supplier Part Number 1=SAM1028-04-ND, Voltage_V=550V
J20: library part CMP-0075404-1, "Header, 100mil, 2x2, Gold, TH", Color=Black, Current_A=6.3A, Manufacturer=Samtec, Supplier Part Number 1=SAM1028-02-ND, Voltage_V=550V
J21 J22 J23 J24: library part CMP-0074916-1, "Terminal Block, 3.5mm Pitch, 3x1, TH", Color=Grey, Current_A=6A, Manufacturer="On-Shore Technology", Supplier Part Number 1=ED1515-ND, Voltage_V=150V
J25: library part CMP-0075421-2, "Header, 100mil, 10x2, Gold, TH", Color=Black, Current_A=6.3A, Manufacturer=Samtec, Supplier Part Number 1=SAM1028-10-ND, Voltage_V=550V
J29: library part HEADER_HSEC8180_EDGE_F2837X, "180 pin (120 + 60) HSEC8 socket, samtec", MANF PART NUMBER="HSEC8-130-01-L-DV-A & HSEC8-160-01-L-DV-A-BL"
J46 J49: library part CMP-0075412-2, "Header, 100mil, 6x2, Gold, TH", Color=Black, Current_A=6.3A, Manufacturer=Samtec, Supplier Part Number 1=SAM1028-06-ND, Voltage_V=550V
L1 L2 L6: library part CMP-0076845-1, "Coupled inductor, 51 µH, 0.2 A, 1 ohm, AEC-Q200 Grade 0, SMD", Manufacturer=TDK, Supplier Part Number 1=445-3958-1-ND, ValueDisplayed=51µH
L3 L7: library part CMP-0084877-1, "Inductor, Ferrite Bead, Ferrite, 3 A, 120 ohm, AEC-Q200 Grade 1, SMD", Manufacturer=MuRata, Value1="120 ohm", Value2=3A
L4: library part CMP-0063383-1, "Inductor, Shielded, 2.2 uH, 8.1 A, 0.0183 ohm, AEC-Q200 Grade 1, SMD", Manufacturer=Vishay-Dale, Supplier Part Number 1=IHLP2525CZER2R2M5A-ND, Value1="0.0183 ohm", Value2=8.1A, ValueDisplayed=2.2uH
L5: library part CMP-0064124-1, "Inductor, Shielded Drum Core, Powdered Iron, 4.7 uH, 7 A, 0.015 ohm, SMD", Manufacturer="Wurth Elektronik", Supplier Part Number 1=732-3389-1-ND, Value1="0.015 ohm", Value2=7A, ValueDisplayed=4.7uH
LBL1: library part CMP-0003625-1, "Thermal Transfer Printable Labels, 0.650\" W x 0.200\" H - 10,000 per roll", Manufacturer=Brady, Supplier Part Number 1=97C5133
Logo1: library part CMP-0074844-1
Logo2: library part CMP-0074839-1
Logo3: library part CMP-0074847-1, "FCC_disclaimer"
Logo4: library part CMP-0074835-1, "IEC 61010-1 High Voltage Warning"
Logo5: library part CMP-0074769-1
Q1 Q2 Q6 Q9: library part CMP-0067562-1, "MOSFET, N-CH, 30 V, 0.3 A, AEC-Q101, SOT-323", Alternate Manufacturer=None, Manufacturer=Rohm, Supplier Part Number 1=78Y8426, Value1="1.1 ohm", Value2="? nC"
Q5: library part CMP-0000870-1, "MOSFET, N-CH, 60 V, 60 A, PowerPAK SO-8", Alternate Manufacturer=None, Manufacturer=Vishay-Semiconductor, Supplier Part Number 1=SIR662DP-T1-GE3CT-ND, Value1=0.002, Value2="96 nC"
Q7 Q8 Q11: library part CMP-0000486-2, "Transistor, NPN, 45 V, 0.1 A, AEC-Q101, SOT-323", Manufacturer="NXP Semiconductor", Supplier Part Number 1=568-6067-1-ND, Value1="0.1 A", Value2=800
Q10: library part CMP-0000013-4, "MOSFET, P-CH, -50 V, -0.15 A, AEC-Q101, SOT-323", Alternate Manufacturer=None, Manufacturer=Nexperia, Value2="0.26 nC"
R1 R161 R217 R218 R219 R220: library part CMP-0027007-2, "RES, 0, 5%, 0.063 W, AEC-Q200 Grade 0, 0402", Manufacturer="KOA Speer", Power_W=63mW, Supplier Part Number 1=660-RK73Z1ETTP, TempCo=ppm/C, Tolerance_%=5%, Value2=0.063W, Value_Code=0000, ValueDisplayed=0
R2 R16 R29 R52 R53 R69 R70 R125 R126 R144 R147 R149 R207: library part CMP-0026918-5, "RES, 3.3 k, 5%, 0.063 W, AEC-Q200 Grade 0, 0402", Manufacturer=Vishay-Dale, Power_W=63mW, Supplier Part Number 1=541-3.3KJCT-ND, TempCo="200 ppm/C", Tolerance_%=5%, Value2=0.063W, Value_Code=3k30, ValueDisplayed=3.3k
R3 R5 R6 R7 R9 R10 R12 R15 R17 R19 R20 R21 R23 R25 R28 R30 R32 R33 R34 R36 R71 R72 R73 R74 R127 R129 R130 R131 R136 R151 R204 R208 R209 R211 R212 R214 R215: library part CMP-0025697-4, "RES, 0, 5%, 0.1 W, AEC-Q200 Grade 0, 0603", Manufacturer=Vishay-Dale, Power_W=100mW, Supplier Part Number 1=541-0.0GCT-ND, TempCo="200 ppm/C", Tolerance_%=5%, Value2=0.1W, Value_Code=0000, ValueDisplayed=0
R4 R14 R18 R27 R31 R206: library part CMP-0081856-1, "RES, 0, 0%, 0.2 W, AEC-Q200 Grade 0, 0402", Manufacturer=Vishay-Dale, Power_W=200mW, Supplier Part Number 1=541-0.0YBTR-ND, Tolerance_%=0%, Value2=0.2W, Value_Code=0, ValueDisplayed=DNP
R8 R13 R22 R26 R35 R205: library part CMP-0017077-1, "RES, 59.0, 1%, 0.25 W, 1206", Manufacturer=Vishay-Dale, Power_W=250mW, Supplier Part Number 1=541-59.0FCT-ND, TempCo="100 ppm/C", Tolerance_%=1%, Value2=0.25W, Value_Code=59R0, ValueDisplayed=59.0
R11 R24 R203: library part CMP-0015444-1, "RES, 120, 1%, 1 W, AEC-Q200 Grade 0, 2512", Manufacturer=Vishay-Dale, Power_W=1W, Supplier Part Number 1=541-120AFCT-ND, TempCo="100 ppm/C", Tolerance_%=1%, Value_Code=120R, ValueDisplayed=DNP
R37 R40 R43 R51 R54 R57 R60 R68: library part CMP-0025825-4, "RES, 51, 5%, 0.1 W, AEC-Q200 Grade 0, 0603", Manufacturer=Vishay-Dale, Power_W=100mW, Supplier Part Number 1=541-51GCT-ND, TempCo="200 ppm/C", Tolerance_%=5%, Value2=0.1W, Value_Code=51R0, ValueDisplayed=51
R38 R55: library part CMP-0025703-4, "RES, 10, 5%, 0.1 W, AEC-Q200 Grade 0, 0603", Manufacturer=Vishay-Dale, Power_W=100mW, Supplier Part Number 1=541-10GCT-ND, TempCo="200 ppm/C", Tolerance_%=5%, Value2=0.1W, Value_Code=10R0, ValueDisplayed=10
R39 R45 R56 R62: library part CMP-0025729-4, "RES, 1.0 k, 5%, 0.1 W, AEC-Q200 Grade 0, 0603", Manufacturer=Vishay-Dale, Power_W=100mW, Supplier Part Number 1=541-1.0KGCT-ND, TempCo="200 ppm/C", Tolerance_%=5%, Value2=0.1W, Value_Code=1k00, ValueDisplayed=1.0k
R41 R46 R47 R48 R49 R58 R63 R64 R65 R66 R120 R128 R134 R135 R141 R142 R143 R146: library part CMP-0026825-5, "RES, 10 k, 5%, 0.063 W, AEC-Q200 Grade 0, 0402", Manufacturer=Vishay-Dale, Power_W=63mW, Supplier Part Number 1=541-10KJCT-ND, TempCo="200 ppm/C", Tolerance_%=5%, Value2=0.063W, Value_Code=10k0, ValueDisplayed=10k
R42 R59 R122 R123 R150: library part CMP-0026823-3, "RES, 100 k, 5%, 0.063 W, AEC-Q200 Grade 0, 0402", Manufacturer=Vishay-Dale, Power_W=63mW, Supplier Part Number 1=541-100KJCT-ND, TempCo="200 ppm/C", Tolerance_%=5%, Value2=0.063W, Value_Code=100k
R44 R61: library part CMP-0026915-3, "RES, 39 k, 5%, 0.063 W, AEC-Q200 Grade 0, 0402", Manufacturer=Vishay-Dale, Power_W=63mW, Supplier Part Number 1=541-39KJCT-ND, TempCo="200 ppm/C", Tolerance_%=5%, Value2=0.063W, Value_Code=39k0, ValueDisplayed=39k
R50 R67: library part CMP-0025962-3, "RES, 10.0 M, 1%, 0.063 W, AEC-Q200 Grade 0, 0402", Manufacturer=Vishay-Dale, Power_W=63mW, Supplier Part Number 1=541-10.0MLCT-ND, TempCo="100 ppm/C", Tolerance_%=1%, Value2=0.063W, Value_Code=10M0, ValueDisplayed=10.0M
R75: library part CMP-0080698-1, "RES, 0, 0%, 1 W, AEC-Q200 Grade 0, 2512", Manufacturer=Kamaya, Power_W=1W, Supplier Part Number 1=791-RMC1JPTE, Tolerance_%=0%, Value_Code=0
R76 R77 R78 R79 R80 R93 R94 R111 R113 R199 R200 R201 R202: library part CMP-0078669-1, "RES, 10.0 k, 1%, 0.063 W, 0402", Manufacturer="Yageo America", Power_W=63mW, Supplier Part Number 1=311-10.0KLRCT-ND, TempCo="100 ppm/C", Tolerance_%=1%, Value2=0.063W, Value_Code=10k0, ValueDisplayed=10.0k
R81: library part CMP-0026743-1, "RES, 820, 1%, 0.063 W, 0402", Manufacturer="Yageo America", Power_W=63mW, Supplier Part Number 1=311-820LRCT-ND, TempCo="100 ppm/C", Tolerance_%=1%, Value2=0.063W, Value_Code=820R, ValueDisplayed=820
R82 R88 R89 R91 R92 R96 R97 R99 R101 R102 R103 R104 R105 R107 R109 R110 R112 R114 R115 R116 R230 R231 R232 R233: library part CMP-0081856-1, "RES, 0, 0%, 0.2 W, AEC-Q200 Grade 0, 0402", Manufacturer=Vishay-Dale, Power_W=200mW, Supplier Part Number 1=541-0.0YBTR-ND, Tolerance_%=0%, Value2=0.2W, Value_Code=0
R83: library part CMP-0022831-5, "RES, 16.0 k, 1%, 0.1 W, 0603", Manufacturer=Yageo, Power_W=100mW, Supplier Part Number 1=311-16.0KHRCT-ND, TempCo="100 ppm/C", Tolerance_%=1%, Value2=0.1W, Value_Code=16k0, ValueDisplayed=16.0k
R84: library part CMP-0082533-1, "RES, 4.99 k, 1%, 0.1 W, 0603", Manufacturer=Vishay-Dale, Power_W=100mW, Supplier Part Number 1=541-3985-1-ND, TempCo="100 ppm/C", Tolerance_%=1%, Value2=0.1W, Value_Code=4k99, ValueDisplayed=4.99k
R85 R86 R87 R95: library part CMP-0026725-1, "RES, 1.00 k, 1%, 0.0625 W, 0402", Manufacturer="Yageo America", Power_W=62.5mW, Supplier Part Number 1=311-1.00KLRCT-ND, TempCo="100 ppm/C", Tolerance_%=1%, Value2=0.0625W, Value_Code=1k00, ValueDisplayed=1.00k
R90: library part CMP-0078583-1, "RES, 15.0 k, 1%, 0.063 W, 0402", Manufacturer="Yageo America", Power_W=63mW, Supplier Part Number 1=311-15.0KLRCT-ND, TempCo="100 ppm/C", Tolerance_%=1%, Value2=0.063W, Value_Code=15k0, ValueDisplayed=15.0k
R98: library part CMP-0026952-5, "RES, 5.6 k, 5%, 0.063 W, AEC-Q200 Grade 0, 0402", Manufacturer=Vishay-Dale, Power_W=63mW, Supplier Part Number 1=541-5.6KJCT-ND, TempCo="200 ppm/C", Tolerance_%=5%, Value2=0.063W, Value_Code=5k60, ValueDisplayed=5.6k
R100: library part CMP-0026834-3, "RES, 12 k, 5%, 0.063 W, AEC-Q200 Grade 0, 0402", Manufacturer=Vishay-Dale, Power_W=63mW, Supplier Part Number 1=541-12KJCT-ND, TempCo="200 ppm/C", Tolerance_%=5%, Value2=0.063W, Value_Code=12k0, ValueDisplayed=12k
R106 R108: library part CMP-0026589-2, "RES, 8.25 k, 1%, 0.063 W, AEC-Q200 Grade 0, 0402", Manufacturer=Vishay-Dale, Power_W=63mW, Supplier Part Number 1=541-8.25KLCT-ND, TempCo="100 ppm/C", Tolerance_%=1%, Value2=0.063W, Value_Code=8k25, ValueDisplayed=8.25k
R117 R118 R119: library part CMP-0026908-3, "RES, 33, 5%, 0.063 W, AEC-Q200 Grade 0, 0402", Manufacturer=Vishay-Dale, Power_W=63mW, Supplier Part Number 1=541-33JCT-ND, TempCo="200 ppm/C", Tolerance_%=5%, Value2=0.063W, Value_Code=33R0, ValueDisplayed=33
R121: library part CMP-0026824-3, "RES, 100, 5%, 0.063 W, AEC-Q200 Grade 0, 0402", Manufacturer=Vishay-Dale, Power_W=63mW, Supplier Part Number 1=541-100JCT-ND, TempCo="200 ppm/C", Tolerance_%=5%, Value2=0.063W, Value_Code=100R, ValueDisplayed=100
R124: library part CMP-0023045-5, "RES, 34.0 k, 1%, 0.1 W, 0603", Manufacturer=Yageo, Power_W=100mW, Supplier Part Number 1=311-34.0KHRCT-ND, TempCo="100 ppm/C", Tolerance_%=1%, Value2=0.1W, Value_Code=34k0, ValueDisplayed=34.0k
R132 R139 R140: library part CMP-0026852-3, "RES, 1.0 k, 5%, 0.063 W, AEC-Q200 Grade 0, 0402", Manufacturer=Vishay-Dale, Power_W=63mW, Supplier Part Number 1=541-1.0KJCT-ND, TempCo="200 ppm/C", Tolerance_%=5%, Value2=0.063W, Value_Code=1k00, ValueDisplayed=1.0k
R133: library part CMP-0023142-5, "RES, 49.9 k, 1%, 0.1 W, 0603", Manufacturer=Yageo, Power_W=100mW, Supplier Part Number 1=311-49.9KHRCT-ND, TempCo="100 ppm/C", Tolerance_%=1%, Value2=0.1W, Value_Code=49k9, ValueDisplayed=49.9k
R137: library part CMP-0023358-4, "RES, 10 M, 0.5%, 0.1 W, AEC-Q200 Grade 0, 0603", Manufacturer=Vishay-Dale, Power_W=100mW, Supplier Part Number 1=541-10MAYCT-ND, TempCo="50 ppm/C", Tolerance_%=0.5%, Value2=0.1W, Value_Code=10M0, ValueDisplayed=10M
R138: library part CMP-0082111-1, "RES, 1.00 M, 0.5%, 0.1 W, AEC-Q200 Grade 0, 0603", Manufacturer=Vishay-Dale, Power_W=100mW, Supplier Part Number 1=541-1.0MAYCT-ND, TempCo="50 ppm/C", Tolerance_%=0.5%, Value2=0.1W, Value_Code=1M00, ValueDisplayed=1.00M
R145 R148: library part CMP-0026966-5, "RES, 6.8 k, 5%, 0.063 W, AEC-Q200 Grade 0, 0402", Manufacturer=Vishay-Dale, Power_W=63mW, Supplier Part Number 1=541-6.8KJCT-ND, TempCo="200 ppm/C", Tolerance_%=5%, Value2=0.063W, Value_Code=6k80, ValueDisplayed=6.8k
R152 R153 R154 R155 R163 R164 R165 R166 R167 R168 R169 R170 R171 R172 R173 R174 R175 R176 R177 R178 R179 R180 R181 R182: library part CMP-0026822-3, "RES, 0, 5%, 0.063 W, AEC-Q200 Grade 0, 0402", Manufacturer=Vishay-Dale, Power_W=63mW, Supplier Part Number 1=541-0.0JCT-ND, TempCo="200 ppm/C", Tolerance_%=5%, Value2=0.063W, Value_Code=0000, ValueDisplayed=0
R156 R157 R158: library part CMP-0026938-5, "RES, 4.7 k, 5%, 0.063 W, AEC-Q200 Grade 0, 0402", Manufacturer=Vishay-Dale, Power_W=63mW, Supplier Part Number 1=541-4.7KJCT-ND, TempCo="200 ppm/C", Tolerance_%=5%, Value2=0.063W, Value_Code=4k70, ValueDisplayed=4.7k
R159 R160 R222 R223: library part CMP-0026412-2, "RES, 4.75 k, 1%, 0.063 W, AEC-Q200 Grade 0, 0402", Manufacturer=Vishay-Dale, Power_W=63mW, Supplier Part Number 1=541-4.75KLCT-ND, TempCo="100 ppm/C", Tolerance_%=1%, Value2=0.063W, Value_Code=4k75, ValueDisplayed=4.75k
R183 R184 R185 R186 R187 R188 R189 R190 R191 R192 R193 R194 R195 R196 R197 R198 R226 R227 R228 R229: library part CMP-0026878-3, "RES, 220, 5%, 0.063 W, AEC-Q200 Grade 0, 0402", Manufacturer=Vishay-Dale, Power_W=63mW, Supplier Part Number 1=541-220JCT-ND, TempCo="200 ppm/C", Tolerance_%=5%, Value2=0.063W, Value_Code=220R, ValueDisplayed=220
R210 R216: library part CMP-0019378-2, "RES, 910, 0.5%, 0.1 W, 0805", Manufacturer="Susumu Co Ltd", Power_W=100mW, Supplier Part Number 1=RR12P910DCT-ND, TempCo="25 ppm/C", Tolerance_%=0.5%, Value2=0.1W, Value_Code=910R, ValueDisplayed=DNP
R213: library part CMP-0021854-2, "RES, 120, 1%, 0.4 W, 0805", Manufacturer=Rohm, Power_W=400mW, Supplier Part Number 1=RHM120AECT-ND, TempCo="100 ppm/C", Tolerance_%=1%, Value2=0.4W, Value_Code=120R, ValueDisplayed=DNP
T1: library part CMP-0030623-1, "Transformer, 105uH, TH", Manufacturer="Wurth Elektronik", ValueDisplayed=105uH
T2 T3: "BMS TRANSFORMER"
U1 U4 U7: library part CMP-0081957-3, "500 mW, High-Efficiency, Low-Emissions, 5 kVRMS Isolated DC-DC Converter, DVE0016A (SO-MOD-16)", Alternate Manufacturer="Texas Instruments", Alternate PartNumber=UCC12050DVER, Operating Temperature Range="-40 to 125 C"
U2 U5 U8: library part CMP-0079585-1, "Isolated CAN Transceiver With 70-V Bus Fault Protection and Flexible Data Rate, DWV0008A (SOIC-8)", Alternate Manufacturer="Texas Instruments", Alternate PartNumber=ISO1042DWV
U3 U6: library part CMP-0001346-1, "24-V, 2-Channel, ESD Protection With 5.7 A of 8/20 µs Surge Protection in a SOT-23 Package", Breakdown Voltage=25.5V, Clamping Voltage=38V, Digikey Part Number=296-ESD762DBZRCT-ND, Manufacturer="Texas Instruments", Mouser Part Number=595-ESD762DBZR, Operating Temperature Range="-50°C to +150°C", PartNumber=ESD752DBZR, ValueDisplayed=1.7pF
U9: library part CMP-0001346-1, "24-V, 2-Channel, ESD Protection With 5.7 A of 8/20 µs Surge Protection in a SOT-23 Package", Breakdown Voltage=25.5V, Clamping Voltage=38V, Digikey Part Number=296-ESD762DBZRCT-ND, Manufacturer="Texas Instruments", Mouser Part Number=595-ESD762DBZR, Operating Temperature Range="-50°C to +150°C", PartNumber=ESD562-SOT23-3, ValueDisplayed=1.7pF
U10 U11: library part CMP-0860051-2, "BQ79600PWQ1, PW0016A (TSSOP-16)", Alternate Manufacturer="Texas Instruments"
U13: library part CMP-0073695-3, "40-V/160-mohm Quad Channels Smart High-Side Switch, PWP0028C (TSSOP-28)", Alternate Manufacturer="Texas Instruments"
U14: library part CMP-0090057-1, "Low IQ Reverse Battery Protection Ideal Diode Controller with Integrated VDS Clamp", Manufacturer="Texas Instruments", Max Supply Voltage=65V, Min Supply Voltage=3.2V, Nominal Supply Current=80uA, Operating Temperature Range="-40°C to +150°C"
U15 U16: library part CMP-04912-000113-1, "50-V, EIGHT-CHANNEL DARLINGTON A"
U17 U18: library part CMP-0093137-1, "12-V Automotive Fully Integrated Solenoid/ Contactor Driver with PWM current regulation, Clamping function & Functional Safety 2 Channels, Single wire Low side interface", Manufacturer="Texas Instruments", Max Supply Voltage=35V, Nominal Supply Current=5mA, Operating Temperature Range=to, Switching Frequency=0.5-25kHz
U19: library part CMP-0001652-1, "Dual 4-Input AND Gates with Schmitt-Trigger Inputs", Digikey Part Number=296-SN74HCS21PWRCT-ND, Manufacturer="Texas Instruments", Max Supply Voltage=6V, Min Supply Voltage=2V, Mouser Part Number=595-SN74HCS21PWR, Nominal Supply Current=0.1uA, Operating Temperature Range="-40°C to +125°C"
U21: library part CMP-0096683-1, "4-V to 36-V, 5-A Synchronous Step-Down DC/DC Converter with Low IQ", Manufacturer="Texas Instruments", Max Supply Voltage=36V, Min Supply Voltage=4V, Nominal Supply Current=25uA, Operating Temperature Range="-40°C to +150°C", Output Voltage=1-16V, Switching Frequency=200-1100kHz
U22: library part CMP-0860463-2, "Automotive 150-mA high-voltage ultra-low-IQ low-dropout (LDO) linear regulator, DRV0006A (WSON-6)", Alternate Manufacturer="Texas Instruments", Operating Temperature Range="-40 to 150 C", Rating=Automotive
U23: library part CMP-0035939-4, "60V, 5uA Iq, 100mA Low-Dropout (LDO) Voltage Regulator With Enable and Power Good, DGN0008C (VSSOP-8)", Alternate Manufacturer="Texas Instruments", Alternate PartNumber=TPS7A1601DGNT, Power Good=TRUE, Rating=Catalog
U24: library part CMP-0860515-1, "Voltage supervisor (reset IC) with watchdog and manual reset, DBV0005A (SOT-23-5)", Alternate Manufacturer="Texas Instruments", Alternate PartNumber=TPS3823-33DBVT, Operating Temperature Range="-40 to 85 C", Rating=Catalog
U25 U26: library part CMP-0066599-1, "Automotive Low-Capacitance 4-Channel +/-15-kV ESD Protection Array for High-Speed Data Interfaces, DBV0006A (SOT-23-6)", Alternate Manufacturer="Texas Instruments"
U27: library part CMP-0075887-1, "Serial RTC with Battery Backup and Trickle Charge, D0008A (SOIC-8)", Alternate Manufacturer="Texas Instruments", Alternate PartNumber=BQ32000D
